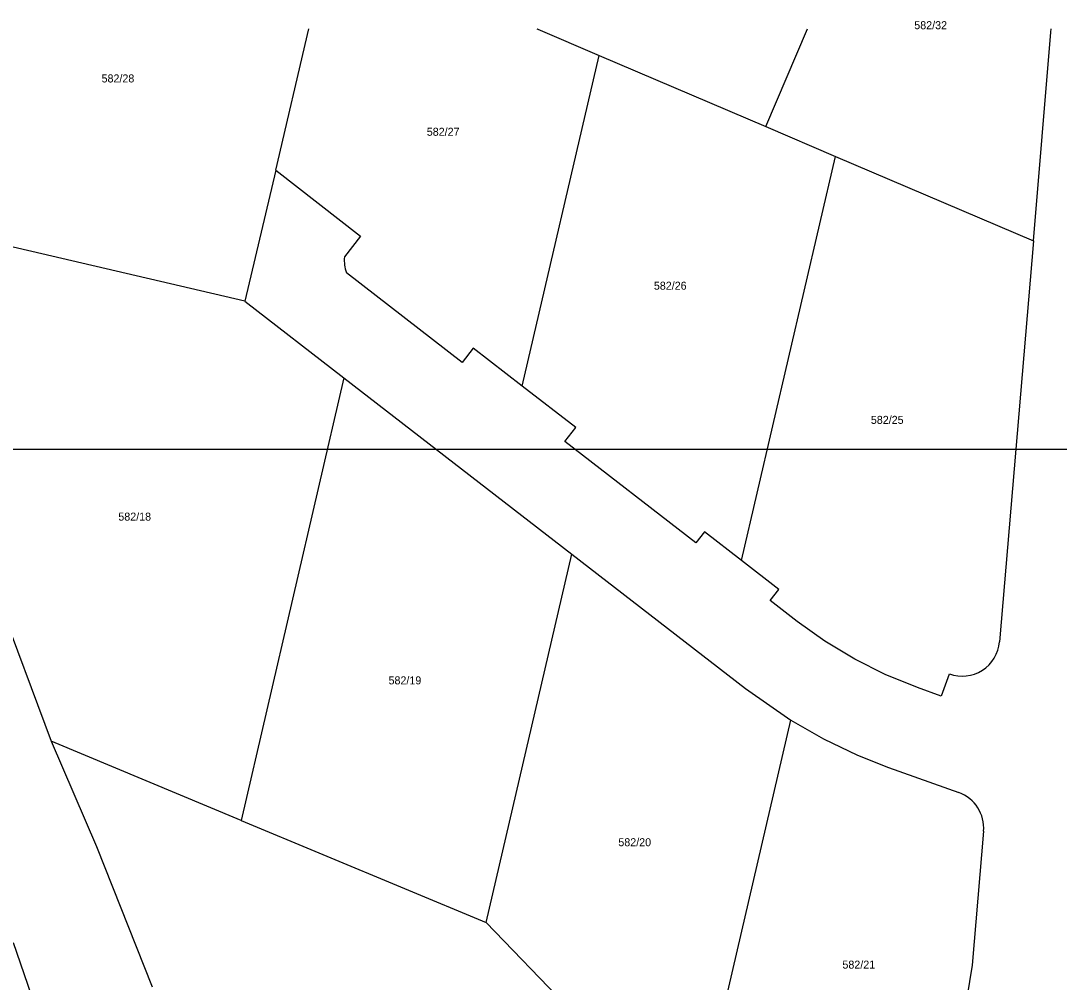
# Model space of a CAD drawing. Extents: x -770973 to -770265, y -1049936 to -1049427.
# Drawn here: x -770637.6 to -770527.3, y -1049529.2 to -1049427.2 of the extents above; entities that cross this region are included whole.
import ezdxf

# ---------------------------------------------------------------- set-up
doc = ezdxf.new("R2010")
doc.units = 0
for name, color, linetype in [('Vrstva 1', 7, 'Continuous'), ('Vrstva 14', 7, 'Continuous'), ('Vrstva 63', 7, 'Continuous')]:
    doc.layers.add(name, color=color, linetype=linetype)

msp = doc.modelspace()

# ---------------------------------------------------------------- linework, layer by layer
at = {"layer": 'Vrstva 1'}
for p, q in [((-770610.51, -1049443.06), (-770606.99, -1049428.06)), ((-770582.77, -1049428.06), (-770582.67, -1049428.1)), ((-770582.65, -1049428.06), (-770582.67, -1049428.1)), ((-770582.67, -1049428.1), (-770576.17, -1049430.87)), ((-770558.48, -1049438.42), (-770554.06, -1049428.06)), ((-770530.06, -1049450.55), (-770528.2, -1049428.39)), ((-770528.2, -1049428.39), (-770528.16, -1049428.06)), ((-770584.34, -1049465.96), (-770576.17, -1049430.87)), ((-770576.17, -1049430.87), (-770558.48, -1049438.42)), ((-770558.48, -1049438.42), (-770551.06, -1049441.59)), ((-770561.05, -1049484.49), (-770551.06, -1049441.59)), ((-770551.06, -1049441.59), (-770530.06, -1049450.55)), ((-770610.51, -1049443.06), (-770613.78, -1049456.97)), ((-770610.51, -1049443.06), (-770601.49, -1049450.04)), ((-770613.78, -1049456.97), (-770644.75, -1049449.76)), ((-770601.49, -1049450.04), (-770603.21, -1049452.26)), ((-770530.06, -1049450.55), (-770533.65, -1049493.11)), ((-770590.7, -1049463.45), (-770602.99, -1049453.94)), ((-770613.78, -1049456.97), (-770603.26, -1049465.11)), ((-770589.54, -1049461.95), (-770590.7, -1049463.45)), ((-770584.34, -1049465.96), (-770589.54, -1049461.95)), ((-770603.26, -1049465.11), (-770614.19, -1049512.07)), ((-770603.26, -1049465.11), (-770579.08, -1049483.82)), ((-770578.66, -1049470.36), (-770584.34, -1049465.96)), ((-770579.82, -1049471.86), (-770578.66, -1049470.36)), ((-770565.92, -1049482.62), (-770579.82, -1049471.86)), ((-770565, -1049481.43), (-770565.92, -1049482.62)), ((-770561.05, -1049484.49), (-770565, -1049481.43)), ((-770588.17, -1049522.9), (-770579.08, -1049483.82)), ((-770579.08, -1049483.82), (-770560.64, -1049498.08)), ((-770557.09, -1049487.55), (-770561.05, -1049484.49)), ((-770640.48, -1049487.25), (-770634.36, -1049503.66)), ((-770558.01, -1049488.74), (-770557.09, -1049487.55)), ((-770555.13, -1049490.97), (-770558.01, -1049488.74)), ((-770552.2, -1049493.06), (-770555.13, -1049490.97)), ((-770549.03, -1049494.97), (-770552.2, -1049493.06)), ((-770545.8, -1049496.58), (-770549.03, -1049494.97)), ((-770542.37, -1049497.97), (-770545.8, -1049496.58)), ((-770538.99, -1049496.53), (-770539.84, -1049498.88)), ((-770560.64, -1049498.08), (-770555.82, -1049501.43)), ((-770539.84, -1049498.88), (-770542.37, -1049497.97)), ((-770566.13, -1049545.75), (-770555.82, -1049501.43)), ((-770555.82, -1049501.43), (-770552.34, -1049503.4)), ((-770634.36, -1049503.66), (-770629.53, -1049514.84)), ((-770614.19, -1049512.07), (-770634.36, -1049503.66)), ((-770552.34, -1049503.4), (-770548.73, -1049505.13)), ((-770548.73, -1049505.13), (-770545.43, -1049506.44)), ((-770545.43, -1049506.44), (-770537.98, -1049509.12)), ((-770614.19, -1049512.07), (-770588.17, -1049522.9)), ((-770535.35, -1049513.22), (-770536.55, -1049527.44)), ((-770629.53, -1049514.84), (-770623.61, -1049529.72)), ((-770588.17, -1049522.9), (-770566.13, -1049545.75)), ((-770629.03, -1049551.97), (-770638.35, -1049525.05)), ((-770536.55, -1049527.44), (-770537.13, -1049530.89))]:
    msp.add_line(p, q, dxfattribs=at)
for centre, radius, start, end in [((-770599.7, -1049452.66), 3.53, 173.5759, 201.3452), ((-770537.63, -1049492.77), 3.99, 250.108, 355.167), ((-770539.35, -1049512.89), 4.02, 355.3553, 70.002)]:
    msp.add_arc(centre, radius, start, end, dxfattribs=at)
at = {"layer": 'Vrstva 63'}
msp.add_lwpolyline([(-770858.67, -1049892.7), (-770264.67, -1049892.7), (-770264.67, -1049472.7), (-770858.67, -1049472.7), (-770858.67, -1049892.7)], dxfattribs=at)

# ---------------------------------------------------------------- texts
at = {"layer": 'Vrstva 14'}
for s, p in [('582/32', (-770542.71, -1049428.09)), ('582/28', (-770629, -1049433.74)), ('582/27', (-770594.47, -1049439.4)), ('582/26', (-770570.36, -1049455.74)), ('582/25', (-770547.32, -1049469.98)), ('582/18', (-770627.22, -1049480.25)), ('582/19', (-770598.53, -1049497.63)), ('582/20', (-770574.13, -1049514.81)), ('582/21', (-770550.34, -1049527.8))]:
    msp.add_text(s, height=0.85, dxfattribs=at).set_placement(p)

doc.saveas('drawing.dxf')
